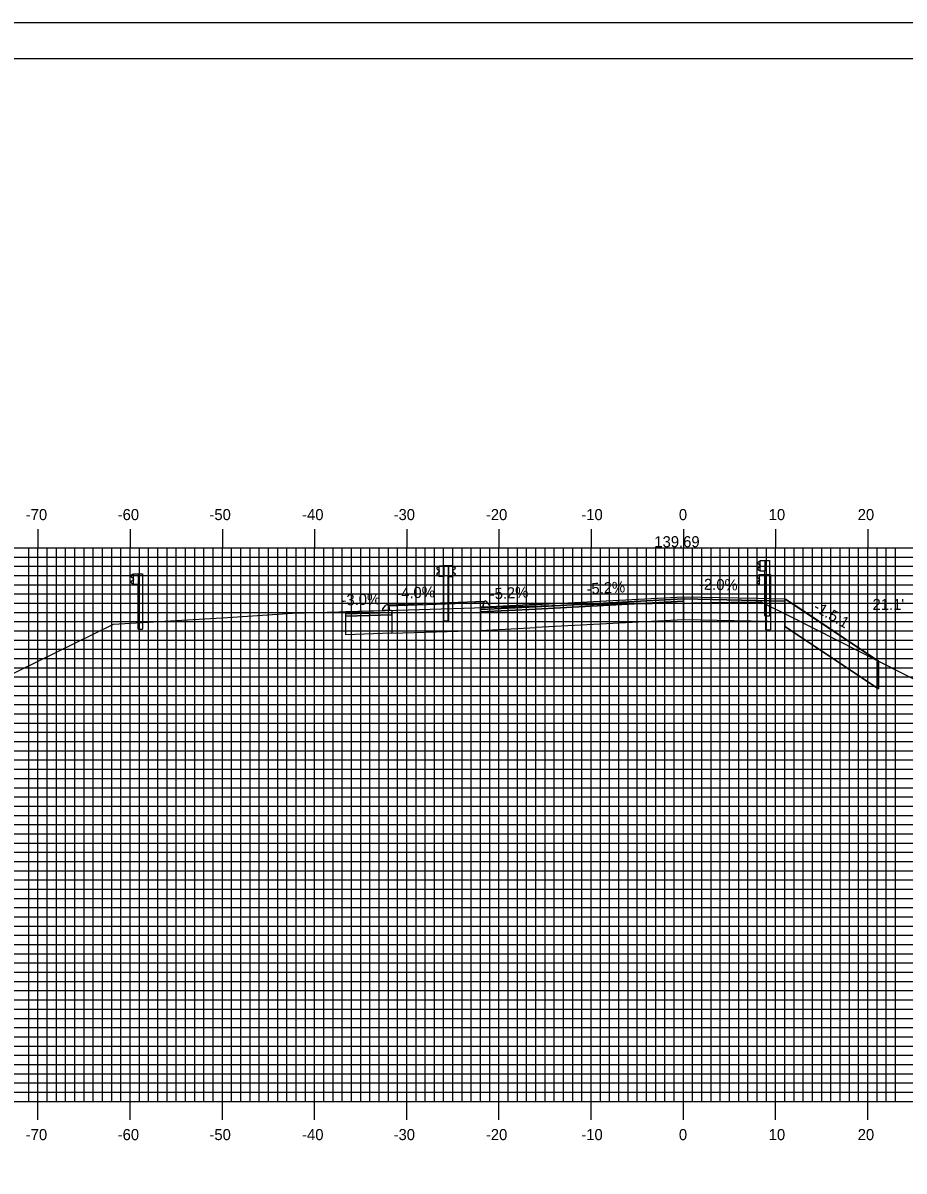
# Model space of a CAD drawing. Extents: x 859865 to 860208, y 364765 to 364985.
# Drawn here: x 859958.8 to 860054.3, y 364860.7 to 364985.2 of the extents above; entities that cross this region are included whole.
import ezdxf

# ---------------------------------------------------------------- set-up
doc = ezdxf.new("R2010")
doc.units = 0
for name, color, linetype in [('ANNOTATION', 7, 'Continuous'), ('BORDER', 7, 'Continuous'), ('D_Curb_Type_3M2_Lt', 7, 'Continuous'), ('D_Curb_Type_3M2_Rt', 7, 'Continuous'), ('D_Guardrail_Beam_Rt', 7, 'Continuous'), ('D_Roadway_Centerline', 7, 'Continuous'), ('D_Roadway_Centerline_Text', 7, 'Continuous'), ('D_Roadway_Edge_Shoulder', 7, 'Continuous'), ('D_Roadway_Edge_TW', 7, 'Continuous'), ('D_Roadway_FinishedGrade', 7, 'Continuous'), ('D_Roadway_Pavement', 7, 'Continuous'), ('D_Roadway_SubGrade', 7, 'Continuous'), ('D_Text_Standard', 7, 'Continuous'), ('H_V ANNOTATION', 7, 'Continuous'), ('M_Guardrail', 7, 'Continuous'), ('M_Roadway_Centerline', 7, 'Continuous'), ('MAJOR', 7, 'Continuous'), ('MINOR', 7, 'Continuous'), ('PATTERNING', 7, 'Continuous'), ('PLOT BOUNDARY', 7, 'Continuous'), ('S_Roadway_Centerline', 7, 'Continuous')]:
    doc.layers.add(name, color=color, linetype=linetype)

msp = doc.modelspace()

# ---------------------------------------------------------------- linework, layer by layer
at = {"layer": 'BORDER'}
msp.add_lwpolyline([(859880.79, 364771.3), (860200.79, 364771.3), (860200.79, 364981.3), (859880.79, 364981.3)], close=True, dxfattribs=at)
at = {"layer": 'D_Curb_Type_3M2_Lt'}
for p, q in [((860008.74, 364922.39), (860008.64, 364921.9)), ((860008.88, 364922.52), (860008.88, 364922.52)), ((860009.39, 364922.06), (860009.03, 364922.47)), ((860008.64, 364921.9), (860009.39, 364921.9)), ((860009.39, 364921.9), (860009.39, 364922.06))]:
    msp.add_line(p, q, dxfattribs=at)
msp.add_arc((860008.91, 364922.36), 0.167, 41.387, 167.6648, dxfattribs=at)
at = {"layer": 'D_Curb_Type_3M2_Rt'}
for p, q in [((859997.78, 364921.68), (859998.13, 364922.08)), ((859997.78, 364921.51), (859997.78, 364921.68)), ((859998.53, 364921.51), (859997.78, 364921.51)), ((859998.42, 364922.01), (859998.53, 364921.51))]:
    msp.add_line(p, q, dxfattribs=at)
msp.add_arc((859998.26, 364921.97), 0.167, 12.3352, 138.613, dxfattribs=at)
at = {"layer": 'D_Guardrail_Beam_Rt'}
for p, q in [((860038.57, 364925.32), (860038.42, 364925.22)), ((860038.42, 364925.07), (860038.62, 364924.94)), ((860038.66, 364925.34), (860038.58, 364925.32)), ((860038.65, 364924.87), (860038.65, 364924.8)), ((860038.66, 364925.42), (860039.34, 364925.42)), ((860038.66, 364924.25), (860038.66, 364925.42)), ((860039.18, 364925.42), (860039.18, 364924.25)), ((860039.28, 364925.42), (860039.28, 364924.25)), ((860039.34, 364925.42), (860039.82, 364925.42)), ((860039.34, 364925.42), (860039.34, 364924.25)), ((860039.82, 364925.42), (860039.82, 364919.42)), ((860038.62, 364924.74), (860038.42, 364924.6)), ((860038.42, 364924.46), (860038.57, 364924.36)), ((860038.58, 364924.35), (860038.66, 364924.34)), ((860039.34, 364924.25), (860038.66, 364924.25)), ((860039.32, 364919.42), (860039.32, 364924.25)), ((860039.32, 364919.42), (860039.82, 364919.42))]:
    msp.add_line(p, q, dxfattribs=at)
for centre, major_axis, start_param, end_param in [((860038.47, 364925.14), (-0.0877, 0), 5.323254, 7.243116), ((860038.59, 364925.28), (-0.0417, 0), 4.907132, 5.323254), ((860038.57, 364924.87), (0.0789, 0), 0, 0.959931), ((860038.47, 364924.53), (-0.0877, 0), 5.323254, 7.243116), ((860038.59, 364924.39), (-0.0417, 0), 0.959931, 1.376053), ((860038.57, 364924.8), (0.0789, 0), 5.323254, 6.283185)]:
    msp.add_ellipse(centre, major_axis=major_axis, ratio=0.995501, start_param=start_param, end_param=end_param, dxfattribs=at)
at = {"layer": 'D_Roadway_Centerline'}
for points in [[(860009.39, 364921.9), (860014.38, 364922.16), (860014.39, 364922.16), (860030.38, 364923), (860030.39, 364923), (860038.38, 364922.84), (860038.39, 364922.84), (860041.39, 364922.78), (860051.56, 364916)], [(859993.78, 364921.38), (859993.8, 364921.38), (859997.72, 364921.5), (859997.78, 364921.5)]]:
    msp.add_lwpolyline(points, dxfattribs=at)
at = {"layer": 'D_Roadway_Edge_Shoulder'}
for points in [[(860030.39, 364923), (860038.39, 364922.84), (860038.39, 364922.84), (860041.39, 364922.78), (860041.39, 364922.53), (860030.39, 364922.75)], [(859993.78, 364921.38), (859997.78, 364921.5), (859998.78, 364921.53), (859998.78, 364921.28), (859993.78, 364921.13)], [(860014.39, 364922.16), (860009.39, 364921.9), (860008.39, 364921.85), (860008.39, 364921.6), (860014.39, 364921.91)]]:
    msp.add_lwpolyline(points, close=True, dxfattribs=at)
at = {"layer": 'D_Roadway_Edge_TW'}
msp.add_lwpolyline([(860014.39, 364922.16), (860030.39, 364923), (860030.39, 364922.75), (860014.39, 364921.91)], close=True, dxfattribs=at)
at = {"layer": 'D_Roadway_FinishedGrade'}
msp.add_line((860041.39, 364922.78), (860041.39, 364919.78), dxfattribs=at)
for points in [[(859998.3, 364922.13), (860008.87, 364922.52)], [(860041.39, 364922.78), (860042.89, 364921.78), (860051.56, 364916)], [(860051.56, 364916), (860051.56, 364913), (860041.39, 364919.78)]]:
    msp.add_lwpolyline(points, dxfattribs=at)
at = {"layer": 'D_Roadway_Pavement'}
for points in [[(860014.39, 364921.91), (860030.39, 364922.75), (860030.39, 364922.5), (860014.39, 364921.66)], [(859993.78, 364921.13), (859998.78, 364921.28), (859998.78, 364921.03), (859993.78, 364920.88)], [(860014.39, 364921.91), (860008.39, 364921.6), (860008.39, 364921.35), (860014.39, 364921.66)]]:
    msp.add_lwpolyline(points, close=True, dxfattribs=at)
msp.add_lwpolyline([(860030.39, 364922.75), (860030.39, 364922.5)], dxfattribs=at)
msp.add_lwpolyline([(860030.39, 364922.75), (860030.39, 364922.5)], dxfattribs=at)
at = {"layer": 'D_Roadway_SubGrade'}
for points in [[(859998.78, 364921.53), (859998.78, 364919.03), (860008.39, 364919.35), (860008.39, 364921.35), (860008.39, 364921.6), (860008.39, 364921.85), (860008.63, 364921.86), (860008.73, 364922.35), (859998.43, 364921.97), (859998.53, 364921.52)], [(860014.39, 364921.66), (860030.39, 364922.5), (860030.39, 364920.5), (860014.39, 364919.66)], [(860030.39, 364922.5), (860030.39, 364922.75), (860041.39, 364922.53), (860041.39, 364922.78), (860041.39, 364920.28), (860030.39, 364920.5)], [(859993.78, 364920.88), (859998.78, 364921.03), (859998.78, 364921.28), (859998.78, 364919.03), (859993.78, 364918.88)], [(860014.39, 364921.66), (860008.39, 364921.35), (860008.39, 364921.6), (860008.39, 364919.35), (860014.39, 364919.66)]]:
    msp.add_lwpolyline(points, close=True, dxfattribs=at)
at = {"layer": 'M_Guardrail'}
for p, q in [((860003.82, 364926.25), (860003.68, 364926.15)), ((860003.92, 364926.27), (860003.84, 364926.25)), ((860003.92, 364926.34), (860004.41, 364926.34)), ((860003.92, 364925.18), (860003.92, 364926.34)), ((860004.39, 364926.34), (860004.39, 364920.34)), ((860004.89, 364926.34), (860004.39, 364926.34)), ((860004.41, 364926.34), (860004.9, 364926.34)), ((860004.41, 364926.34), (860004.41, 364925.18)), ((860005.38, 364926.34), (860004.89, 364926.34)), ((860004.89, 364926.34), (860004.89, 364925.18)), ((860004.9, 364926.34), (860004.9, 364920.34)), ((860005.38, 364925.18), (860005.38, 364926.34)), ((860005.38, 364926.27), (860005.46, 364926.26)), ((860005.47, 364926.25), (860005.62, 364926.15)), ((860038.63, 364926.83), (860038.49, 364926.73)), ((860038.49, 364926.58), (860038.68, 364926.45)), ((860038.68, 364926.23), (860038.49, 364926.09)), ((860038.73, 364926.85), (860038.65, 364926.83)), ((860038.72, 364926.38), (860038.72, 364926.29)), ((860038.73, 364926.92), (860039.22, 364926.92)), ((860038.73, 364925.75), (860038.73, 364926.92)), ((860039.22, 364926.92), (860039.71, 364926.92)), ((860039.22, 364926.92), (860039.22, 364925.75)), ((860039.71, 364926.92), (860039.71, 364920.92)), ((859970.66, 364925.4), (859970.51, 364925.3)), ((859970.51, 364925.15), (859970.71, 364925.02)), ((859970.76, 364925.42), (859970.67, 364925.4)), ((859970.74, 364924.95), (859970.74, 364924.86)), ((859970.76, 364925.49), (859971.25, 364925.49)), ((859970.76, 364924.32), (859970.76, 364925.49)), ((859971.25, 364925.49), (859971.74, 364925.49)), ((859971.25, 364925.49), (859971.25, 364924.32)), ((859971.74, 364925.49), (859971.74, 364919.49)), ((860003.68, 364926), (860003.87, 364925.87)), ((860003.87, 364925.65), (860003.68, 364925.51)), ((860003.68, 364925.37), (860003.82, 364925.27)), ((860003.84, 364925.26), (860003.92, 364925.25)), ((860003.9, 364925.8), (860003.9, 364925.71)), ((860004.41, 364925.18), (860003.92, 364925.18)), ((860004.41, 364920.34), (860004.41, 364925.18)), ((860004.89, 364920.34), (860004.89, 364925.18)), ((860004.89, 364925.18), (860005.38, 364925.18)), ((860005.46, 364925.27), (860005.38, 364925.25)), ((860005.39, 364925.81), (860005.39, 364925.72)), ((860005.62, 364926.01), (860005.42, 364925.87)), ((860005.42, 364925.65), (860005.62, 364925.52)), ((860005.62, 364925.37), (860005.47, 364925.27)), ((860038.49, 364925.95), (860038.63, 364925.85)), ((860038.65, 364925.84), (860038.73, 364925.83)), ((860039.22, 364925.75), (860038.73, 364925.75)), ((860039.22, 364920.92), (860039.22, 364925.75)), ((859970.71, 364924.8), (859970.51, 364924.66)), ((859970.51, 364924.52), (859970.66, 364924.42)), ((859970.67, 364924.41), (859970.76, 364924.4)), ((859971.25, 364924.32), (859970.76, 364924.32)), ((859971.25, 364919.49), (859971.25, 364924.32)), ((860004.89, 364920.34), (860004.39, 364920.34)), ((860004.41, 364920.34), (860004.9, 364920.34)), ((860039.22, 364920.92), (860039.71, 364920.92)), ((859971.25, 364919.49), (859971.74, 364919.49))]:
    msp.add_line(p, q, dxfattribs=at)
for centre, major_axis, start_param, end_param in [((860003.73, 364926.08), (-0.0877, 0), 5.323254, 7.243116), ((860003.84, 364926.21), (-0.0417, 0), 4.886922, 5.323254), ((860005.45, 364926.22), (0.0417, 0), 0.959931, 1.396263), ((860005.57, 364926.08), (0.0877, 0), 5.323254, 7.243116), ((860038.54, 364926.65), (-0.0877, 0), 5.323254, 7.243116), ((860038.54, 364926.02), (-0.0877, 0), 5.323254, 7.243116), ((860038.65, 364926.79), (-0.0417, 0), 4.886922, 5.323254), ((860038.64, 364926.38), (0.0789, 0), 0, 0.959931), ((860038.64, 364926.29), (0.0789, 0), 5.323254, 6.283185), ((859970.56, 364925.22), (-0.0877, 0), 5.323254, 7.243116), ((859970.68, 364925.36), (-0.0417, 0), 4.886922, 5.323254), ((859970.66, 364924.95), (0.0789, 0), 0, 0.959931), ((859970.66, 364924.86), (0.0789, 0), 5.323254, 6.283185), ((860003.73, 364925.44), (-0.0877, 0), 5.323254, 7.243116), ((860003.84, 364925.3), (-0.0417, 0), 0.959931, 1.396263), ((860003.83, 364925.8), (0.0789, 0), 0, 0.959931), ((860003.83, 364925.71), (0.0789, 0), 5.323254, 6.283185), ((860005.47, 364925.81), (-0.0789, 0), 5.323254, 6.283185), ((860005.47, 364925.72), (-0.0789, 0), 6.283185, 7.243116), ((860005.45, 364925.31), (0.0417, 0), 4.886922, 5.323254), ((860005.57, 364925.44), (0.0877, 0), 5.323254, 7.243116), ((860038.65, 364925.88), (-0.0417, 0), 0.959931, 1.396263), ((859970.56, 364924.59), (-0.0877, 0), 5.323254, 7.243116), ((859970.68, 364924.45), (-0.0417, 0), 0.959931, 1.396263)]:
    msp.add_ellipse(centre, major_axis=major_axis, ratio=0.995501, start_param=start_param, end_param=end_param, dxfattribs=at)
at = {"layer": 'MAJOR'}
for p, q in [((859960.39, 364930.31), (859960.39, 364928.3)), ((859970.39, 364930.31), (859970.39, 364928.3)), ((859980.39, 364930.31), (859980.39, 364928.3)), ((859990.39, 364930.31), (859990.39, 364928.3)), ((860000.39, 364930.31), (860000.39, 364928.3)), ((860010.39, 364930.31), (860010.39, 364928.3)), ((860020.39, 364930.31), (860020.39, 364928.3)), ((860030.39, 364930.31), (860030.39, 364928.3)), ((860040.39, 364930.31), (860040.39, 364928.3)), ((860050.39, 364930.31), (860050.39, 364928.3)), ((859890.39, 364928.3), (860170.39, 364928.3)), ((859890.39, 364928.3), (860170.39, 364928.3)), ((859960.39, 364868.3), (859960.39, 364928.3)), ((859970.39, 364868.3), (859970.39, 364928.3)), ((859980.39, 364868.3), (859980.39, 364928.3)), ((859990.39, 364868.3), (859990.39, 364928.3)), ((860000.39, 364868.3), (860000.39, 364928.3)), ((860010.39, 364868.3), (860010.39, 364928.3)), ((860020.39, 364868.3), (860020.39, 364928.3)), ((860030.39, 364868.3), (860030.39, 364928.3)), ((860040.39, 364868.3), (860040.39, 364928.3)), ((860050.39, 364868.3), (860050.39, 364928.3)), ((859890.39, 364923.3), (860170.39, 364923.3)), ((859890.39, 364918.3), (860170.39, 364918.3)), ((859890.39, 364913.3), (860170.39, 364913.3)), ((859890.39, 364908.3), (860170.39, 364908.3)), ((859890.39, 364903.3), (860170.39, 364903.3)), ((859890.39, 364898.3), (860170.39, 364898.3)), ((859890.39, 364893.3), (860170.39, 364893.3)), ((859890.39, 364888.3), (860170.39, 364888.3)), ((859890.39, 364883.3), (860170.39, 364883.3)), ((859890.39, 364878.3), (860170.39, 364878.3)), ((859890.39, 364873.3), (860170.39, 364873.3)), ((859890.39, 364868.3), (860170.39, 364868.3)), ((859890.39, 364868.3), (860170.39, 364868.3)), ((859960.39, 364866.3), (859960.39, 364868.3)), ((859970.39, 364866.3), (859970.39, 364868.3)), ((859980.39, 364866.3), (859980.39, 364868.3)), ((859990.39, 364866.3), (859990.39, 364868.3)), ((860000.39, 364866.3), (860000.39, 364868.3)), ((860010.39, 364866.3), (860010.39, 364868.3)), ((860020.39, 364866.3), (860020.39, 364868.3)), ((860030.39, 364866.3), (860030.39, 364868.3)), ((860040.39, 364866.3), (860040.39, 364868.3)), ((860050.39, 364866.3), (860050.39, 364868.3))]:
    msp.add_line(p, q, dxfattribs=at)
at = {"layer": 'MINOR'}
for p, q in [((859959.39, 364868.3), (859959.39, 364928.3)), ((859961.39, 364868.3), (859961.39, 364928.3)), ((859962.39, 364868.3), (859962.39, 364928.3)), ((859963.39, 364868.3), (859963.39, 364928.3)), ((859964.39, 364868.3), (859964.39, 364928.3)), ((859965.39, 364868.3), (859965.39, 364928.3)), ((859966.39, 364868.3), (859966.39, 364928.3)), ((859967.39, 364868.3), (859967.39, 364928.3)), ((859968.39, 364868.3), (859968.39, 364928.3)), ((859969.39, 364868.3), (859969.39, 364928.3)), ((859971.39, 364868.3), (859971.39, 364928.3)), ((859972.39, 364868.3), (859972.39, 364928.3)), ((859973.39, 364868.3), (859973.39, 364928.3)), ((859974.39, 364868.3), (859974.39, 364928.3)), ((859975.39, 364868.3), (859975.39, 364928.3)), ((859976.39, 364868.3), (859976.39, 364928.3)), ((859977.39, 364868.3), (859977.39, 364928.3)), ((859978.39, 364868.3), (859978.39, 364928.3)), ((859979.39, 364868.3), (859979.39, 364928.3)), ((859981.39, 364868.3), (859981.39, 364928.3)), ((859982.39, 364868.3), (859982.39, 364928.3)), ((859983.39, 364868.3), (859983.39, 364928.3)), ((859984.39, 364868.3), (859984.39, 364928.3)), ((859985.39, 364868.3), (859985.39, 364928.3)), ((859986.39, 364868.3), (859986.39, 364928.3)), ((859987.39, 364868.3), (859987.39, 364928.3)), ((859988.39, 364868.3), (859988.39, 364928.3)), ((859989.39, 364868.3), (859989.39, 364928.3)), ((859991.39, 364868.3), (859991.39, 364928.3)), ((859992.39, 364868.3), (859992.39, 364928.3)), ((859993.39, 364868.3), (859993.39, 364928.3)), ((859994.39, 364868.3), (859994.39, 364928.3)), ((859995.39, 364868.3), (859995.39, 364928.3)), ((859996.39, 364868.3), (859996.39, 364928.3)), ((859997.39, 364868.3), (859997.39, 364928.3)), ((859998.39, 364868.3), (859998.39, 364928.3)), ((859999.39, 364868.3), (859999.39, 364928.3)), ((860001.39, 364868.3), (860001.39, 364928.3)), ((860002.39, 364868.3), (860002.39, 364928.3)), ((860003.39, 364868.3), (860003.39, 364928.3)), ((860004.39, 364868.3), (860004.39, 364928.3)), ((860005.39, 364868.3), (860005.39, 364928.3)), ((860006.39, 364868.3), (860006.39, 364928.3)), ((860007.39, 364868.3), (860007.39, 364928.3)), ((860008.39, 364868.3), (860008.39, 364928.3)), ((860009.39, 364868.3), (860009.39, 364928.3)), ((860011.39, 364868.3), (860011.39, 364928.3)), ((860012.39, 364868.3), (860012.39, 364928.3)), ((860013.39, 364868.3), (860013.39, 364928.3)), ((860014.39, 364868.3), (860014.39, 364928.3)), ((860015.39, 364868.3), (860015.39, 364928.3)), ((860016.39, 364868.3), (860016.39, 364928.3)), ((860017.39, 364868.3), (860017.39, 364928.3)), ((860018.39, 364868.3), (860018.39, 364928.3)), ((860019.39, 364868.3), (860019.39, 364928.3)), ((860021.39, 364868.3), (860021.39, 364928.3)), ((860022.39, 364868.3), (860022.39, 364928.3)), ((860023.39, 364868.3), (860023.39, 364928.3)), ((860024.39, 364868.3), (860024.39, 364928.3)), ((860025.39, 364868.3), (860025.39, 364928.3)), ((860026.39, 364868.3), (860026.39, 364928.3)), ((860027.39, 364868.3), (860027.39, 364928.3)), ((860028.39, 364868.3), (860028.39, 364928.3)), ((860029.39, 364868.3), (860029.39, 364928.3)), ((860031.39, 364868.3), (860031.39, 364928.3)), ((860032.39, 364868.3), (860032.39, 364928.3)), ((860033.39, 364868.3), (860033.39, 364928.3)), ((860034.39, 364868.3), (860034.39, 364928.3)), ((860035.39, 364868.3), (860035.39, 364928.3)), ((860036.39, 364868.3), (860036.39, 364928.3)), ((860037.39, 364868.3), (860037.39, 364928.3)), ((860038.39, 364868.3), (860038.39, 364928.3)), ((860039.39, 364868.3), (860039.39, 364928.3)), ((860041.39, 364868.3), (860041.39, 364928.3)), ((860042.39, 364868.3), (860042.39, 364928.3)), ((860043.39, 364868.3), (860043.39, 364928.3)), ((860044.39, 364868.3), (860044.39, 364928.3)), ((860045.39, 364868.3), (860045.39, 364928.3)), ((860046.39, 364868.3), (860046.39, 364928.3)), ((860047.39, 364868.3), (860047.39, 364928.3)), ((860048.39, 364868.3), (860048.39, 364928.3)), ((860049.39, 364868.3), (860049.39, 364928.3)), ((860051.39, 364868.3), (860051.39, 364928.3)), ((860052.39, 364868.3), (860052.39, 364928.3)), ((860053.39, 364868.3), (860053.39, 364928.3)), ((859890.39, 364927.3), (860170.39, 364927.3)), ((859890.39, 364926.3), (860170.39, 364926.3)), ((859890.39, 364925.3), (860170.39, 364925.3)), ((859890.39, 364924.3), (860170.39, 364924.3)), ((859890.39, 364922.3), (860170.39, 364922.3)), ((859890.39, 364921.3), (860170.39, 364921.3)), ((859890.39, 364920.3), (860170.39, 364920.3)), ((859890.39, 364919.3), (860170.39, 364919.3)), ((859890.39, 364917.3), (860170.39, 364917.3)), ((859890.39, 364916.3), (860170.39, 364916.3)), ((859890.39, 364915.3), (860170.39, 364915.3)), ((859890.39, 364914.3), (860170.39, 364914.3)), ((859890.39, 364912.3), (860170.39, 364912.3)), ((859890.39, 364911.3), (860170.39, 364911.3)), ((859890.39, 364910.3), (860170.39, 364910.3)), ((859890.39, 364909.3), (860170.39, 364909.3)), ((859890.39, 364907.3), (860170.39, 364907.3)), ((859890.39, 364906.3), (860170.39, 364906.3)), ((859890.39, 364905.3), (860170.39, 364905.3)), ((859890.39, 364904.3), (860170.39, 364904.3)), ((859890.39, 364902.3), (860170.39, 364902.3)), ((859890.39, 364901.3), (860170.39, 364901.3)), ((859890.39, 364900.3), (860170.39, 364900.3)), ((859890.39, 364899.3), (860170.39, 364899.3)), ((859890.39, 364897.3), (860170.39, 364897.3)), ((859890.39, 364896.3), (860170.39, 364896.3)), ((859890.39, 364895.3), (860170.39, 364895.3)), ((859890.39, 364894.3), (860170.39, 364894.3)), ((859890.39, 364892.3), (860170.39, 364892.3)), ((859890.39, 364891.3), (860170.39, 364891.3)), ((859890.39, 364890.3), (860170.39, 364890.3)), ((859890.39, 364889.3), (860170.39, 364889.3)), ((859890.39, 364887.3), (860170.39, 364887.3)), ((859890.39, 364886.3), (860170.39, 364886.3)), ((859890.39, 364885.3), (860170.39, 364885.3)), ((859890.39, 364884.3), (860170.39, 364884.3)), ((859890.39, 364882.3), (860170.39, 364882.3)), ((859890.39, 364881.3), (860170.39, 364881.3)), ((859890.39, 364880.3), (860170.39, 364880.3)), ((859890.39, 364879.3), (860170.39, 364879.3)), ((859890.39, 364877.3), (860170.39, 364877.3)), ((859890.39, 364876.3), (860170.39, 364876.3)), ((859890.39, 364875.3), (860170.39, 364875.3)), ((859890.39, 364874.3), (860170.39, 364874.3)), ((859890.39, 364872.3), (860170.39, 364872.3)), ((859890.39, 364871.3), (860170.39, 364871.3)), ((859890.39, 364870.3), (860170.39, 364870.3)), ((859890.39, 364869.3), (860170.39, 364869.3))]:
    msp.add_line(p, q, dxfattribs=at)
at = {"layer": 'PATTERNING'}
msp.add_line((860041.39, 364920.28), (860041.39, 364919.78), dxfattribs=at)
for points in [[(860051.56, 364916), (860042.89, 364921.78), (860041.39, 364922.78)], [(860041.39, 364922.78), (860041.39, 364922.53), (860041.39, 364920.28), (860041.39, 364920.28)], [(860041.39, 364919.78), (860051.56, 364913), (860051.56, 364916)]]:
    msp.add_lwpolyline(points, dxfattribs=at)
at = {"layer": 'PLOT BOUNDARY'}
msp.add_lwpolyline([(859864.6, 364765.18), (860204.6, 364765.18), (860204.6, 364985.18), (859864.6, 364985.18)], close=True, dxfattribs=at)
at = {"layer": 'S_Roadway_Centerline'}
msp.add_lwpolyline([(859890.39, 364895.26), (859891.97, 364895.23), (859902.52, 364895.12), (859905.19, 364895.32), (859912.41, 364896.41), (859918.87, 364897.52), (859922.54, 364899.01), (859936.06, 364904.11), (859958.29, 364914.96), (859968.57, 364920.02), (859980.94, 364920.76), (859988.01, 364921.21), (860000.55, 364921.58), (860018.51, 364922.11), (860035.53, 364922.39), (860038.79, 364922.46), (860042.21, 364920.74), (860061.3, 364911.05)], dxfattribs=at)

# ---------------------------------------------------------------- texts
at = {"layer": 'ANNOTATION'}
for s, rotation, p in [('-2.0%', 358.8541, (860032.07, 364923.76)), ('-4.0%', 2.2626, (859999.27, 364922.77)), ('-5.2%', 2.9996, (860009.41, 364922.7)), ('-5.2%', 2.9981, (860019.91, 364923.25)), ('-3.0%', 1.7078, (859993.33, 364922.04)), ('-1.5:1', 330.177, (860044.38, 364921.56))]:
    msp.add_text(s, height=1.2, rotation=rotation, dxfattribs=at).set_placement(p)
at = {"layer": 'D_Roadway_Centerline_Text'}
msp.add_text('139.69', height=1.2, dxfattribs=at).set_placement((860027.24, 364928.36))
at = {"layer": 'D_Text_Standard'}
msp.add_text("21.1'", height=1.2, dxfattribs=at).set_placement((860050.9, 364921.56))
at = {"layer": 'H_V ANNOTATION'}
for s, p in [('-70', (859959.07, 364931.3)), ('-60', (859969.04, 364931.3)), ('-50', (859978.99, 364931.3)), ('-40', (859989.04, 364931.3)), ('-30', (859998.96, 364931.3)), ('-20', (860008.97, 364931.3)), ('-10', (860019.32, 364931.3)), ('0', (860029.9, 364931.3)), ('10', (860039.64, 364931.3)), ('20', (860049.29, 364931.3)), ('-70', (859959.07, 364864.1)), ('-60', (859969.04, 364864.1)), ('-50', (859978.99, 364864.1)), ('-40', (859989.04, 364864.1)), ('-30', (859998.96, 364864.1)), ('-20', (860008.97, 364864.1)), ('-10', (860019.32, 364864.1)), ('0', (860029.9, 364864.1)), ('10', (860039.64, 364864.1)), ('20', (860049.29, 364864.1))]:
    msp.add_text(s, height=1.2, dxfattribs=at).set_placement(p)
at = {"layer": 'M_Roadway_Centerline'}
for s, p in [('C', (859988, 364921.21)), ('L', (859988.01, 364921.2)), ('C', (860018.51, 364922.11)), ('L', (860018.51, 364922.1))]:
    msp.add_text(s, height=0.0146, dxfattribs=at).set_placement(p)

doc.saveas('drawing.dxf')
